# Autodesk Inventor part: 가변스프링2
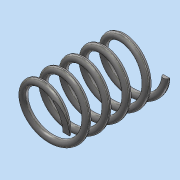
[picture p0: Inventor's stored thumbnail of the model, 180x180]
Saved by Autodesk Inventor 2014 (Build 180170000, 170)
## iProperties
Created: 2018-10
Part Number: 가변스프링2
Material: 스테인레스 스틸
Document SubType Name: Modeling
Designer: kb542
Density: 8.08 g/cm^3
Appearance: 반연마
Mass: 6.29345 g
Surface Area: 15.8114 cm^2
Volume: 0.778892 cm^3
Author: kb542
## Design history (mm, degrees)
sketch "스케치1"
  geometry: L1 (0, 0)-(8, 0); L2 (8, 0)-(8, 30.472); L3 (8, 30.472)-(0, 30.472); L4 (0, 30.472)-(0, 0); C1 r 1 at (8, 0)
  constraints: 8 end point, 2 parallel, 1 centre point, 1 coincident, 1 horizontal, 1 perpendicular
  dimensions: "d0" = 30.47206 distance between parallel lines of L1 L3 (derived); "d1" = 2 diameter of C1; "d2" = 16 diameter of L2 L4
feature "코일1" sketch "스케치1" pitch "d3" = 10; turns "d5" = 5; dims "d4" = 30.47206 (= d0), "d6" = 0, angle "d7" = 90 deg, angle "d8" = 90 deg, "d9" = 0, "d10" = 0
sketch "스케치2"
  geometry: L1 (-7, 0)-(-9, 0) reference; 1 further point
  constraints: 1 horizontal alignment
extrude "돌출1" cut sketch "스케치2" distance "d11" = 10; taper "d12" = 0 deg
node "작업 평면1"
sketch "스케치3"
  geometry: L1 (-9, 0)-(-7, 0) reference; 1 further point
  constraints: 1 horizontal alignment
extrude "돌출2" cut sketch "스케치3" distance "d13" = 10; taper "d14" = 0 deg
node "솔리드1"
node "절단 모서리 투영1"
node "절단 모서리 투영2"
